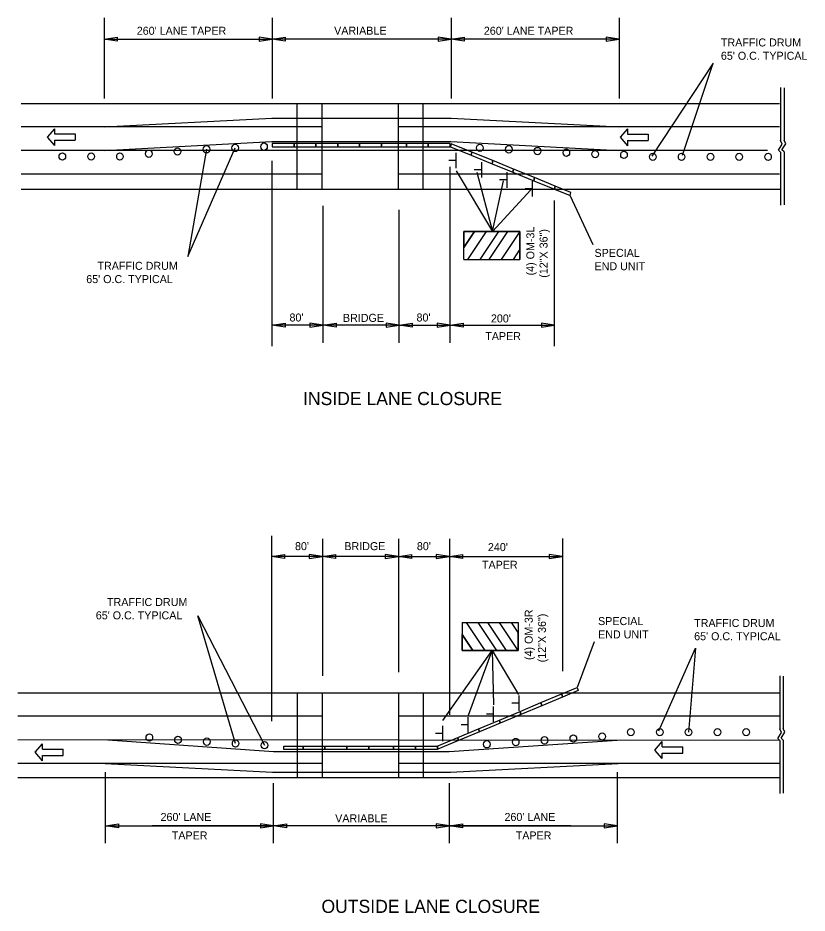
# Model space of a CAD drawing. Extents: x 13528 to 25043, y 7635 to 10612.
# Drawn here: x 23774 to 24375, y 9686 to 10368 of the extents above; entities that cross this region are included whole.
import ezdxf

# ---------------------------------------------------------------- set-up
doc = ezdxf.new("R2010")
doc.units = 0
for name, color, linetype in [('Default', 7, 'Continuous'), ('R_Border', 7, 'Continuous'), ('STAMP_PE_CRAFTON', 7, 'Continuous'), ('STAMP_PE_FOSTER', 7, 'Continuous'), ('STAMP_PE_TXT', 7, 'Continuous'), ('STAMP_PRELIMINARY', 7, 'Continuous')]:
    doc.layers.add(name, color=color, linetype=linetype)

msp = doc.modelspace()

# ---------------------------------------------------------------- linework, layer by layer
at = {"layer": 'Default'}
for p, q in [((23839.21, 10367.65), (23839.21, 10306.18)), ((23967.23, 10367.65), (23967.23, 10306.18)), ((24103.58, 10367.65), (24103.58, 10306.18)), ((24231.61, 10367.65), (24231.61, 10306.18)), ((23967.23, 10364.35), (23967.23, 10306.18)), ((24103.58, 10364.35), (24103.58, 10306.18)), ((23839.21, 10351.37), (23967.23, 10351.37)), ((24103.58, 10351.37), (23967.23, 10351.37)), ((24231.61, 10351.37), (24103.58, 10351.37)), ((24303.15, 10333.15), (24256.37, 10262.2)), ((24279.73, 10262.99), (24303.15, 10333.15)), ((24354.53, 10314.67), (24354.53, 10274.18)), ((24357.11, 10314.25), (24357.11, 10274.46)), ((24082.04, 10302.19), (23776.15, 10302.19)), ((23986.32, 10236.86), (23986.32, 10302.19)), ((24082.04, 10302.19), (23986.32, 10302.19)), ((24005.2, 10236.86), (24005.2, 10302.19)), ((24063.15, 10302.19), (24063.15, 10236.86)), ((24082.04, 10302.19), (24082.04, 10236.86)), ((24353.69, 10302.19), (24082.04, 10302.19)), ((24005.2, 10284.67), (23776.15, 10284.67)), ((24353.69, 10284.67), (24063.15, 10284.67)), ((23801.36, 10283.23), (23795.79, 10276.8)), ((23801.36, 10283.23), (23801.36, 10279.21)), ((23801.36, 10279.21), (23817.12, 10279.21)), ((23817.12, 10279.21), (23817.12, 10274.39)), ((24237.98, 10283.11), (24232.42, 10276.69)), ((24237.98, 10283.11), (24237.98, 10279.1)), ((24237.98, 10279.1), (24253.74, 10279.1)), ((24253.74, 10279.1), (24253.74, 10274.28)), ((23795.79, 10276.8), (23801.36, 10270.37)), ((23801.36, 10274.39), (23817.12, 10274.39)), ((23801.36, 10274.39), (23801.36, 10270.37)), ((24232.42, 10276.69), (24237.98, 10270.26)), ((24237.98, 10274.28), (24253.74, 10274.28)), ((24237.98, 10274.28), (24237.98, 10270.26)), ((24344.49, 10266.67), (23776.15, 10266.67)), ((23902.89, 10185.77), (23938.96, 10268.57)), ((23917.15, 10267.56), (23902.89, 10185.77)), ((24107.18, 10264.96), (24107.18, 10253.23)), ((24354.53, 10265.37), (24354.53, 10224.92)), ((24354.53, 10265.37), (24354.53, 10224.92)), ((24357.11, 10265.64), (24357.11, 10225.2)), ((24357.11, 10265.64), (24357.11, 10225.2)), ((23967.23, 10117.68), (23967.23, 10258.83)), ((24107.07, 10259.13), (24101.73, 10259.13)), ((24126.57, 10257.73), (24126.57, 10245.99)), ((24102.8, 10120.03), (24102.8, 10254.1)), ((24126.45, 10251.89), (24121.11, 10251.89)), ((24145.91, 10250.01), (24145.91, 10238.28)), ((24005.2, 10248.67), (23776.15, 10248.67)), ((24353.69, 10248.67), (24063.15, 10248.67)), ((24145.79, 10244.18), (24140.45, 10244.18)), ((24165.3, 10243.4), (24165.3, 10231.66)), ((24082.88, 10236.86), (23776.15, 10236.86)), ((24082.04, 10236.86), (23986.32, 10236.86)), ((24354.53, 10236.86), (24082.88, 10236.86)), ((24165.18, 10237.56), (24159.84, 10237.56)), ((24211.78, 10194.84), (24194.25, 10232.33)), ((24006.04, 10120.03), (24006.04, 10224.46)), ((24182.34, 10117.58), (24182.34, 10228.54)), ((24064, 10120.03), (24064, 10221.52)), ((24006.04, 10133.49), (23967.23, 10133.49)), ((24064, 10133.49), (24006.04, 10133.49)), ((24064, 10133.49), (24102.8, 10133.49)), ((24102.8, 10133.49), (24182.34, 10133.49)), ((23966.66, 9973.18), (23966.66, 9831.98)), ((24005.47, 9970.79), (24005.47, 9866.35)), ((24063.42, 9970.79), (24063.42, 9869.29)), ((24102.23, 9970.79), (24102.23, 9836.72)), ((24188.33, 9971.05), (24188.33, 9870.13)), ((24005.47, 9957.33), (23966.66, 9957.33)), ((24063.42, 9957.33), (24005.47, 9957.33)), ((24063.42, 9957.33), (24092.69, 9957.33)), ((24092.69, 9957.33), (24188.33, 9957.33)), ((23939.4, 9814.91), (23910.56, 9912.1)), ((23910.56, 9912.1), (23961.34, 9813.56)), ((24212.49, 9892.38), (24199.66, 9857.58)), ((24353.96, 9866.51), (24353.96, 9826.02)), ((24356.54, 9866.09), (24356.54, 9826.29)), ((23986.59, 9853.27), (23773.57, 9853.27)), ((23986.59, 9788.7), (23986.59, 9853.27)), ((24082.31, 9853.27), (23986.59, 9853.27)), ((24005.47, 9788.7), (24005.47, 9853.27)), ((24063.42, 9853.27), (24063.42, 9788.7)), ((24082.31, 9853.27), (24082.31, 9788.7)), ((24353.96, 9853.27), (24082.31, 9853.27)), ((24155.33, 9839.77), (24155.33, 9851.51)), ((24135.94, 9831.47), (24135.94, 9843.2)), ((24155.21, 9845.61), (24149.87, 9845.61)), ((24005.47, 9835.74), (23773.57, 9835.74)), ((24353.96, 9835.74), (24063.42, 9835.74)), ((24116.59, 9823.2), (24116.59, 9834.93)), ((24135.82, 9837.3), (24130.48, 9837.3)), ((24097.21, 9816.57), (24097.21, 9828.3)), ((24116.48, 9829.03), (24111.14, 9829.03)), ((24097.1, 9822.41), (24091.76, 9822.41)), ((24353.96, 9817.2), (23773.57, 9817.74)), ((23786.71, 9808.19), (23792.28, 9814.61)), ((23792.28, 9810.6), (23792.28, 9814.61)), ((24258.77, 9809.95), (24264.33, 9816.37)), ((24264.33, 9812.36), (24264.33, 9816.37)), ((24353.96, 9817.2), (24353.96, 9776.76)), ((24353.96, 9817.2), (24353.96, 9776.76)), ((24356.54, 9817.48), (24356.54, 9777.03)), ((24356.54, 9817.48), (24356.54, 9777.03)), ((23792.28, 9801.76), (23786.71, 9808.19)), ((23792.28, 9810.6), (23808.04, 9810.6)), ((23808.04, 9805.78), (23808.04, 9810.6)), ((24264.33, 9803.52), (24258.77, 9809.95)), ((24264.33, 9812.36), (24280.09, 9812.36)), ((24264.33, 9807.54), (24280.09, 9807.54)), ((24264.33, 9803.52), (24264.33, 9807.54)), ((24280.09, 9807.54), (24280.09, 9812.36)), ((24005.47, 9799.74), (23773.57, 9799.74)), ((23792.28, 9805.78), (23808.04, 9805.78)), ((23792.28, 9801.76), (23792.28, 9805.78)), ((23839.98, 9799.74), (23967.47, 9793.05)), ((24353.96, 9799.74), (24063.42, 9799.74)), ((24103.04, 9793.05), (24230.78, 9799.74)), ((23840.26, 9739.09), (23840.26, 9792.95)), ((23967.47, 9793.05), (24103.04, 9793.05)), ((24230.25, 9739.09), (24230.25, 9792.95)), ((24082.31, 9788.7), (23773.57, 9788.7)), ((24082.31, 9788.7), (23986.59, 9788.7)), ((24353.96, 9788.7), (24082.31, 9788.7)), ((23968.28, 9739.09), (23968.28, 9784.72)), ((24102.23, 9739.09), (24102.23, 9784.72)), ((23840.26, 9752.08), (23968.28, 9752.08)), ((23968.28, 9752.08), (23875.79, 9752.08)), ((23904.11, 9752.08), (23968.28, 9752.08)), ((24102.23, 9752.08), (23968.28, 9752.08)), ((24194.72, 9752.08), (24102.23, 9752.08)), ((24102.23, 9752.08), (24230.25, 9752.08))]:
    msp.add_line(p, q, dxfattribs=at)
for points in [[(23839.21, 10351.37), (23849.21, 10352.87), (23849.21, 10349.87)], [(23967.23, 10351.37), (23957.23, 10352.87), (23957.23, 10349.87)], [(23967.23, 10351.37), (23977.23, 10352.87), (23977.23, 10349.87)], [(24103.58, 10351.37), (24093.58, 10352.87), (24093.58, 10349.87)], [(24103.58, 10351.37), (24113.58, 10352.87), (24113.58, 10349.87)], [(24231.61, 10351.37), (24221.61, 10352.87), (24221.61, 10349.87)], [(23967.23, 10133.49), (23977.23, 10134.99), (23977.23, 10131.99)], [(24006.04, 10133.49), (23996.04, 10134.99), (23996.04, 10131.99)], [(24006.04, 10133.49), (24016.04, 10134.99), (24016.04, 10131.99)], [(24064, 10133.49), (24054, 10134.99), (24054, 10131.99)], [(24064, 10133.49), (24074, 10134.99), (24074, 10131.99)], [(24102.8, 10133.49), (24092.8, 10134.99), (24092.8, 10131.99)], [(24102.8, 10133.49), (24112.8, 10134.99), (24112.8, 10131.99)], [(24182.34, 10133.49), (24172.34, 10134.99), (24172.34, 10131.99)], [(23966.66, 9957.33), (23976.66, 9958.83), (23976.66, 9955.83)], [(24005.47, 9957.33), (23995.47, 9958.83), (23995.47, 9955.83)], [(24005.47, 9957.33), (24015.47, 9958.83), (24015.47, 9955.83)], [(24063.42, 9957.33), (24053.42, 9958.83), (24053.42, 9955.83)], [(24063.42, 9957.33), (24073.42, 9958.83), (24073.42, 9955.83)], [(24102.23, 9957.33), (24092.23, 9958.83), (24092.23, 9955.83)], [(24102.23, 9957.33), (24112.23, 9958.83), (24112.23, 9955.83)], [(24188.33, 9957.33), (24178.33, 9958.83), (24178.33, 9955.83)], [(23840.26, 9752.08), (23850.26, 9753.58), (23850.26, 9750.58)], [(23968.28, 9752.08), (23958.28, 9753.58), (23958.28, 9750.58)], [(23968.28, 9752.08), (23978.28, 9753.58), (23978.28, 9750.58)], [(24102.23, 9752.08), (24092.23, 9753.58), (24092.23, 9750.58)], [(24102.23, 9752.08), (24112.23, 9753.58), (24112.23, 9750.58)], [(24230.25, 9752.08), (24220.25, 9753.58), (24220.25, 9750.58)]]:
    msp.add_lwpolyline(points, close=True, dxfattribs=at)
for points in [[(23839.21, 10284.67), (23966.88, 10291.39), (24103.58, 10291.39), (24231.61, 10284.67)], [(23839.47, 10266.67), (23966.95, 10273.38), (24103.28, 10273.38), (24231.19, 10266.67)], [(24354.53, 10265.37), (24352.88, 10266.84), (24355.83, 10271.41), (24354.53, 10274.18)], [(24354.53, 10265.37), (24352.88, 10266.84), (24355.83, 10271.41), (24354.53, 10274.18)], [(24357.11, 10265.64), (24355.46, 10267.12), (24358.41, 10271.69), (24357.11, 10274.46)], [(24357.11, 10265.64), (24355.46, 10267.12), (24358.41, 10271.69), (24357.11, 10274.46)], [(24107.44, 10251.22), (24134.97, 10204.96), (24164.26, 10236.59)], [(24123.12, 10250.09), (24134.97, 10204.96), (24143.48, 10243.42)], [(24097.15, 9832.34), (24134.9, 9885.86), (24154.9, 9852.23)], [(24116.68, 9836.52), (24134.9, 9885.86), (24135.94, 9844.31)], [(24261.87, 9824.58), (24289.57, 9887.4), (24284.42, 9823.58)], [(24353.96, 9817.2), (24352.31, 9818.68), (24355.26, 9823.24), (24353.96, 9826.02)], [(24353.96, 9817.2), (24352.31, 9818.68), (24355.26, 9823.24), (24353.96, 9826.02)], [(24356.54, 9817.48), (24354.89, 9818.96), (24357.84, 9823.52), (24356.54, 9826.29)], [(24356.54, 9817.48), (24354.89, 9818.96), (24357.84, 9823.52), (24356.54, 9826.29)], [(23842.1, 9817.68), (23968.36, 9808.87), (24102.1, 9808.87), (24229.97, 9817.32)]]:
    msp.add_lwpolyline(points, dxfattribs=at)
at = {"layer": 'R_Border'}
for centre in [(23917.15, 10267.56), (23939.09, 10268.58), (23961.04, 10269.57), (24125.49, 10268.6), (24147.43, 10267.51), (23807.41, 10262.11), (23829.36, 10262.11), (23851.31, 10262.11), (23873.25, 10264.18), (23895.2, 10265.9), (24169.38, 10266.21), (24191.33, 10265), (24213.28, 10263.8), (24235.22, 10263.26), (24257.17, 10261.81), (24279.12, 10261.81), (24301.06, 10261.81), (24323.01, 10261.81), (24344.96, 10261.81), (23873.69, 9819.51), (23895.5, 9817.65), (24174.68, 9817.31), (24196.63, 9818.73), (24218.58, 9820.19), (24240.52, 9823.58), (24262.47, 9823.58), (24284.42, 9823.58), (24306.37, 9823.58), (24328.31, 9823.58), (23917.45, 9816.31), (23939.4, 9814.91), (23961.34, 9813.56), (24130.79, 9814.3), (24152.74, 9816)]:
    msp.add_ellipse(centre, major_axis=(0, 2.81), ratio=0.888889, dxfattribs=at)
at = {"layer": 'STAMP_PE_FOSTER'}
for p, q in [((24113.19, 10183.61), (24113.19, 10204.96)), ((24113.19, 10183.61), (24155.88, 10183.61)), ((24111.94, 9907.2), (24154.62, 9907.2)), ((24111.94, 9907.2), (24111.94, 9885.86))]:
    msp.add_line(p, q, dxfattribs=at)
msp.add_lwpolyline([(24113.19, 10204.96), (24155.88, 10204.96), (24155.88, 10183.61)], dxfattribs=at)
at = {"layer": 'STAMP_PE_TXT'}
for points in [[(23967.23, 10269.48), (23983.89, 10269.48), (23983.89, 10271.98), (23967.23, 10271.98)], [(23983.89, 10269.48), (24000.54, 10269.48), (24000.54, 10271.98), (23983.89, 10271.98)], [(24000.54, 10269.48), (24017.2, 10269.48), (24017.2, 10271.98), (24000.54, 10271.98)], [(24017.2, 10269.48), (24033.85, 10269.48), (24033.85, 10271.98), (24017.2, 10271.98)], [(24033.85, 10269.48), (24050.5, 10269.48), (24050.5, 10271.98), (24033.85, 10271.98)], [(24050.5, 10269.48), (24069.5, 10269.48), (24069.5, 10271.98), (24050.5, 10271.98)], [(24069.5, 10269.48), (24086.15, 10269.48), (24086.15, 10271.98), (24069.5, 10271.98)], [(24086.15, 10269.48), (24102.8, 10269.48), (24102.8, 10271.98), (24086.15, 10271.98)], [(24102.95, 10269.43), (24118.83, 10262.98), (24119.34, 10265.39), (24103.46, 10271.84)], [(24118.83, 10262.98), (24134.7, 10256.52), (24135.22, 10258.94), (24119.34, 10265.39)], [(24134.7, 10256.52), (24150.58, 10250.07), (24151.1, 10252.48), (24135.22, 10258.94)], [(24150.58, 10250.07), (24166.46, 10243.62), (24166.98, 10246.03), (24151.1, 10252.48)], [(24166.46, 10243.62), (24182.34, 10237.17), (24182.86, 10239.58), (24166.98, 10246.03)], [(24182.34, 10237.17), (24194.25, 10232.33), (24194.77, 10234.74), (24182.86, 10239.58)], [(24187.8, 9852.63), (24199.66, 9857.58), (24200.2, 9855.17), (24188.33, 9850.22)], [(24171.98, 9846.01), (24187.8, 9852.63), (24188.33, 9850.22), (24172.52, 9843.6)], [(24156.16, 9839.38), (24171.98, 9846.01), (24172.52, 9843.6), (24156.7, 9836.98)], [(24140.35, 9832.76), (24156.16, 9839.38), (24156.7, 9836.98), (24140.89, 9830.36)], [(24124.53, 9826.14), (24140.35, 9832.76), (24140.89, 9830.36), (24125.07, 9823.73)], [(24108.71, 9819.52), (24124.53, 9826.14), (24125.07, 9823.73), (24109.25, 9817.11)], [(24092.9, 9812.9), (24108.71, 9819.52), (24109.25, 9817.11), (24093.44, 9810.49)], [(23976.2, 9812.93), (23990.81, 9812.93), (23990.81, 9810.43), (23976.2, 9810.43)], [(23990.81, 9812.93), (24007.46, 9812.93), (24007.46, 9810.43), (23990.81, 9810.43)], [(24007.46, 9812.93), (24024.12, 9812.93), (24024.12, 9810.43), (24007.46, 9810.43)], [(24024.12, 9812.93), (24040.77, 9812.93), (24040.77, 9810.43), (24024.12, 9810.43)], [(24040.77, 9812.93), (24059.76, 9812.93), (24059.76, 9810.43), (24040.77, 9810.43)], [(24059.76, 9812.93), (24076.42, 9812.93), (24076.42, 9810.43), (24059.76, 9810.43)], [(24076.42, 9812.93), (24093.07, 9812.93), (24093.07, 9810.43), (24076.42, 9810.43)]]:
    msp.add_lwpolyline(points, close=True, dxfattribs=at)
at = {"layer": 'STAMP_PRELIMINARY'}
for p, q in [((24121.29, 10204.96), (24113.19, 10192.82)), ((24113.19, 10204.96), (24155.88, 10204.96)), ((24113.19, 10204.96), (24113.19, 10192.82)), ((24113.19, 10192.82), (24121.29, 10204.96)), ((24121.29, 10204.96), (24113.19, 10204.96)), ((24116.3, 10183.71), (24130.46, 10204.96)), ((24155.88, 10204.96), (24121.29, 10204.96)), ((24139.66, 10204.96), (24125.49, 10183.71)), ((24130.46, 10204.96), (24139.66, 10204.96)), ((24132.52, 10183.71), (24146.68, 10204.96)), ((24155.88, 10204.96), (24141.65, 10183.61)), ((24146.68, 10204.96), (24155.88, 10204.96)), ((24155.88, 10183.61), (24155.88, 10204.96)), ((24155.88, 10204.96), (24155.88, 10191.42)), ((24155.88, 10191.42), (24150.69, 10183.64)), ((24155.88, 10191.42), (24150.69, 10183.64)), ((24155.88, 10183.61), (24155.88, 10191.42)), ((24150.69, 10183.64), (24155.88, 10183.61)), ((24115.04, 9907.11), (24129.21, 9885.86)), ((24138.4, 9885.86), (24124.23, 9907.11)), ((24131.26, 9907.11), (24145.43, 9885.86)), ((24154.62, 9885.86), (24140.39, 9907.2)), ((24149.44, 9907.17), (24154.62, 9907.2)), ((24154.62, 9899.4), (24149.44, 9907.17)), ((24154.62, 9899.4), (24149.44, 9907.17)), ((24154.62, 9907.2), (24154.62, 9885.86)), ((24154.62, 9907.2), (24154.62, 9899.4)), ((24120.03, 9885.86), (24111.94, 9898)), ((24111.94, 9885.86), (24111.94, 9898)), ((24111.94, 9898), (24120.03, 9885.86)), ((24154.62, 9885.86), (24154.62, 9899.4)), ((24111.94, 9885.86), (24154.62, 9885.86)), ((24120.03, 9885.86), (24111.94, 9885.86)), ((24154.62, 9885.86), (24120.03, 9885.86)), ((24129.21, 9885.86), (24138.4, 9885.86)), ((24145.43, 9885.86), (24154.62, 9885.86))]:
    msp.add_line(p, q, dxfattribs=at)

# ---------------------------------------------------------------- texts
at = {"layer": 'Default'}
for s, height, p in [("260' LANE TAPER", 6.1, (23864.1, 10354.8)), ('VARIABLE', 6.1, (24014.44, 10354.88)), ("260' LANE TAPER", 6.1, (24128.47, 10354.8)), ('TRAFFIC DRUM', 6.1, (24309.04, 10345.89)), ("65' O.C. TYPICAL", 6.1, (24309.04, 10335.76)), ('SPECIAL', 6.1, (24212.78, 10185.59)), ('TRAFFIC DRUM', 6.1, (23834.18, 10175.74)), ('END UNIT', 6.1, (24212.78, 10175.46)), ("65' O.C. TYPICAL", 6.1, (23825.63, 10165.62)), ("80'", 6.1, (23980.44, 10136.37)), ('BRIDGE', 6.1, (24021.15, 10136.1)), ("80'", 6.1, (24077.2, 10136.37)), ("200'", 6.1, (24133.86, 10135.67)), ('TAPER', 6.1, (24129.56, 10122.17)), ('INSIDE LANE CLOSURE ', 10.002, (23990.76, 10072.69)), ("80'", 6.1, (23984.64, 9962.19)), ('BRIDGE', 6.1, (24022.23, 9962.19)), ("80'", 6.1, (24077.47, 9962.19)), ('TRAFFIC DRUM', 6.1, (23841.45, 9919.62)), ("65' O.C. TYPICAL", 6.1, (23832.9, 9909.49)), ('SPECIAL', 6.1, (24215.49, 9905.1)), ('TRAFFIC DRUM', 6.1, (24288.67, 9903.67)), ('END UNIT', 6.1, (24215.49, 9894.97)), ("65' O.C. TYPICAL", 6.1, (24288.67, 9893.55)), ("260' LANE", 6.1, (23882.22, 9755.88)), ('VARIABLE', 6.1, (24015.26, 9754.86)), ("260' LANE", 6.1, (24144.2, 9755.88)), ('TAPER', 6.1, (23890.79, 9741.81)), ('OUTSIDE LANE CLOSURE', 10.002, (24004.79, 9685.85))]:
    msp.add_text(s, height=height, dxfattribs=at).set_placement(p)
for s, p in [("240'", (24131.58, 9961.49)), ('TAPER', (24127.04, 9947.99)), ('TAPER', (24152.77, 9741.81))]:
    msp.add_text(s, height=6.1, rotation=360, dxfattribs=at).set_placement(p)
at = {"layer": 'STAMP_PE_CRAFTON'}
for s, p in [('(4) OM-3L', (24166.97, 10171.47)), ('(12"X 36")', (24177.02, 10169.7)), ('(4) OM-3R', (24165.71, 9878.51)), ('(12"X 36")', (24175.76, 9876.73))]:
    msp.add_text(s, height=6.1, rotation=90, dxfattribs=at).set_placement(p)

doc.saveas('drawing.dxf')
